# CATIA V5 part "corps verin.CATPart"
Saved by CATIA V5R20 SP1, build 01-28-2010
Part number: corps verin
Bounding box of the stored display mesh (mm): x 175.67 to 324.33, y -49.995 to 502.924, z 443.179 to 899.996
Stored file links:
  C:\Users\Nicolas\Documents\Ifma\2A\S3\iao\projet\corps verin.CATPart
  C:\Users\Nicolas\Documents\Ifma\2A\S3\iao\projet\Product1.CATProduct
  C:\Users\Nicolas\Documents\Ifma\2A\S3\iao\projet\bielle2.CATPart
  C:\Users\Nicolas\Documents\Ifma\2A\S3\iao\projet\triangle.CATPart
  C:\Users\Nicolas\Documents\Ifma\2A\S3\iao\projet\bielle1.CATPart
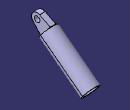
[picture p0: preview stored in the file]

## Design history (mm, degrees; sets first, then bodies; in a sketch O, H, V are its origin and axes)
Set1
  Plane1: linked copy from another document
  Point1: linked copy from another document
  Line1: linked copy from another document
Body1 (main body)
  Sketch1 on Plane1, origin (250, 0, 0), H (0, 1, 0), V (0, 0, 1)
    construction line L1 (830, 220) -> (0, 850)
    point P1 (830, 220)
    point P2 (0, 850)
    reference projected point E1 (0, 850) from Point1
    reference projected point E2 (830, 220) from Line1
    arc A1 centre (0, 850) radius 50 from (22.2228, 894.79) to (-37.1637, 816.5507) ccw
    point P3 (39.8266, 819.7702)
    line L2 (37.3314, 733.7831) -> (121.9749, 845.2976)
    point P4 (37.3314, 733.7831)
    point P5 (121.9749, 845.2976)
    line L3 (121.9749, 845.2976) -> (22.2228, 894.79)
    line L4 (37.3314, 733.7831) -> (-37.1637, 816.5507)
    point P7 (37.3314, 733.7831)
    radius A1 = 50
    length L2 = 140
    distance L2 P2 = 100
    distance P5 L1 = 70
    coincidence: P2 E1, P1 E2, A1 P3, P3 L1, P7 L2, P7 P4
    perpendicularity: L2 L1
    tangency: L3 A1, L4 A1
  Pad1: profile Sketch1, direction (1, 0, 0), length 25, mirrored extent
  Sketch2 on face of Pad1 from Sketch1.L2, origin (0, -291.9706, 299.9408), H (-1, 0, 0), V (0, 0.6046, 0.7965)
    circle A1 centre (-250, 614.6641) radius 74.3303
    reference projected point E1 (-275, 544.6641) from vertex [face of Pad1 from Sketch1.L2 | end face of Pad1 | face of Pad1 from Sketch1.L4]
    reference projected point E2 (-225, 684.6641) from vertex [face of Pad1 from Sketch1.L3 | start face of Pad1 | face of Pad1 from Sketch1.L2]
    reference projected point E3 (-275, 684.6641) from vertex [face of Pad1 from Sketch1.L3 | end face of Pad1 | face of Pad1 from Sketch1.L2]
    coincidence: A1 E1, E2 A1, E3 A1
  Pad2: profile Sketch2, direction (0, 0.7965, -0.6046), length 25
  Sketch3 on end face of Pad2, origin (0, -274.1164, 282.113), H (-1, 0, 0), V (0, 0.6046, 0.7965)
    circle A1 centre (-250, 618.0699) radius 74.3303
    circle A2 centre (-250, 618.0699) radius 60
    reference projected circle E1 centre (-250, 618.0699) radius 74.3303 from edge [face of Pad2 from Sketch2.A1 | end face of Pad2]
    radius A2 = 60
    coincidence: A1 E1
    concentricity: A2 A1
  Pad3: profile Sketch3, direction (0, 0.7965, -0.6046), length 450
  Sketch4 on end face of Pad1, origin (275, 0, 850), H (0, 1, 0), V (0, 0, 1)
    point P1 (0, 0)
    reference projected point E1 (0, 0) from Point1
    coincidence: E1 P1
  Hole1: placed by Sketch4, at (275, 0, 850) direction (-1, 0, 0), diameter 50, through (limit type 3)
  Fillet1: radius 5, on edge [face of Pad1 from Sketch1.L3 | start face of Pad2]; edge [start face of Pad2 | end face of Pad1]; edge [start face of Pad2 | face of Pad1 from Sketch1.L4]; edge [start face of Pad1 | start face of Pad2]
